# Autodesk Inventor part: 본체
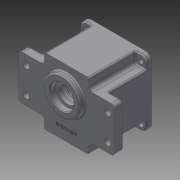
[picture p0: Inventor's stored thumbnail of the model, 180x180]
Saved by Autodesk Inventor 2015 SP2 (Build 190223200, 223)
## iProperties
Created: 2015-06
Part Number: 본체
Material: 일반
Document SubType Name: Modeling
Designer: AMC
Density: 1 g/cm^3
Appearance: 기본값
Author: AMC
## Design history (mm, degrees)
sketch "스케치4"
  geometry: L1 (-65, 30)-(65, 30); L2 (65, 30)-(65, -30); L3 (65, -30)-(-65, -30); L4 (-65, -30)-(-65, 30); 5 further points
  constraints: 8 end point, 4 midpoint, 2 horizontal alignment, 2 vertical alignment
  dimensions: "d22" = 130 distance of L2.end L3.end; "d23" = 60 distance of L1.end L2.end; "d24" = 60 distance of L3.end L1.start; "d25" = 130 distance of L1.start L1.end
extrude "돌출3" new body sketch "스케치4" distance "d26" = 12; taper "d27" = 0 deg
fillet "모깎기2" dims "d34" = 5
sketch "스케치10"
  geometry: L1 (30, -45)-(-30, -45); L2 (-30, -45)-(-30, 45); L3 (-30, 45)-(30, 45); L4 (30, 45)-(30, -45); 5 further points
  constraints: 8 end point, 4 midpoint, 2 horizontal alignment, 2 vertical alignment
  dimensions: "d57" = 60 distance of L2.end L3.end; "d58" = 90 distance of L1.end L2.end; "d59" = 60 distance of L1.start L1.end; "d60" = 90 distance of L3.end L1.start
extrude "돌출9" join sketch "스케치10" distance "d61" = 63; taper "d62" = 0 deg
sketch "스케치11"
  geometry: L1 (-30, -45)-(30, -45) reference; L2 (30, -45)-(30, 45) reference; L3 (30, 45)-(-30, 45) reference; L4 (-30, 45)-(-30, -45) reference; L5 (-45, 45)-(45, 45); L6 (45, 45)-(45, -45); L7 (45, -45)-(-45, -45); L8 (-45, -45)-(-45, 45); 5 further points
  constraints: 8 end point, 4 midpoint, 2 horizontal alignment, 2 vertical alignment
  dimensions: "d63" = 90 distance of L6.end L7.end; "d64" = 90 distance of L5.end L6.end; "d65" = 90 distance of L5.start L5.end; "d66" = 90 distance of L7.end L5.start
extrude "돌출10" join sketch "스케치11" distance "d67" = 7; taper "d68" = 0 deg
sketch "스케치12"
  geometry: L1 (-30, -45)-(-30, 45) reference; L2 (30, 45)-(30, -45) reference; L3 (30, -45)-(45, -45) reference; L4 (45, -45)-(45, 45) reference; L5 (45, 45)-(30, 45) reference; L6 (-30, 45)-(-45, 45) reference; L7 (-45, 45)-(-45, -45) reference; L8 (-45, -45)-(-30, -45) reference; C1 r 3.5 at (37, -37); C2 r 3.5 at (-37, -37); C3 r 3.5 at (-37, 37); C4 r 3.5 at (37, 37); 1 further point
  constraints: 4 centre point, 2 horizontal alignment, 2 vertical alignment
  dimensions: "d72" = 7 diameter of C1; "d73" = 7 diameter of C2; "d74" = 7 diameter of C3; "d75" = 7 diameter of C4; "d76" = 74 distance of C2.centre C1.centre; "d77" = 37 horizontal distance of point (0, 0) C1.centre; "d78" = 74 distance of C4.centre C1.centre; "d79" = 37 horizontal distance of point (0, 0) C4.centre
extrude "돌출11" cut sketch "스케치12" stored distance "d80" = 7; taper "d81" = 0 deg
sketch "스케치13"
  geometry: L1 (-60, -30)-(-30, -30) reference; L2 (65, -25)-(65, 25) reference; L3 (60, 30)-(30, 30) reference; L4 (30, 45)-(30, 30) reference; L5 (-30, 45)-(30, 45) reference; L6 (-30, -45)-(-30, -30) reference; L7 (-65, 25)-(-65, -25) reference; L8 (30, -45)-(-30, -45) reference; L9 (30, -30)-(60, -30) reference; L10 (-30, 30)-(-30, 45) reference; L11 (-30, 30)-(-60, 30) reference; L12 (30, -30)-(30, -45) reference; C1 r 4.5 at (55, -17.5); C2 r 4.5 at (-55, -17.5); C3 r 4.5 at (-55, 17.5); C4 r 4.5 at (55, 17.5); A1 r 5 centre (60, -25) between (60, -30) and (65, -25) reference; A2 r 5 centre (60, 25) between (65, 25) and (60, 30) reference; A3 r 5 centre (-60, 25) between (-60, 30) and (-65, 25) reference; A4 r 5 centre (-60, -25) between (-65, -25) and (-60, -30) reference; 1 further point
  constraints: 4 centre point, 2 horizontal alignment, 2 vertical alignment
  dimensions: "d82" = 9 diameter of C1; "d83" = 9 diameter of C2; "d84" = 9 diameter of C3; "d85" = 9 diameter of C4; "d86" = 110 distance of C1.centre C2.centre; "d87" = 55 horizontal distance of point (0, 0) C1.centre; "d88" = 35 distance of C1.centre C4.centre; "d89" = 17.5 vertical distance of C4.centre point (0, 0)
extrude "돌출12" cut sketch "스케치13" stored distance "d90" = 7; taper "d91" = 0 deg
sketch "스케치14"
  geometry: C1 r 25 at (0, -11); 1 further point
  constraints: 1 centre point, 1 vertical alignment
  dimensions: "d93" = 50 diameter of C1; "d94" = 11 distance of point (0, 0) C1.centre
extrude "돌출13" join sketch "스케치14" distance "d95" = 7; taper "d96" = 0 deg
fillet "모깎기9" dims "d97" = 2
sketch "스케치15"
  geometry: L1 (-38, 0)-(-45, 0) reference; L2 (-45, 0)-(-45, 70) reference; L3 (-45, 70)-(45, 70) reference; L4 (45, 70)-(45, 0) reference; L5 (45, 0)-(16, 0) reference; L6 (14, -2)-(14, -5) reference; L7 (12, -7)-(-34, -7) reference; L8 (-36, -5)-(-36, -2) reference; L9 (12, -7)-(-34, -7) reference; L10 (-11, -7)-(-11, 70); L11 (-11, -7)-(-27, -7); L12 (-27, -7)-(-27, 1); L13 (-27, 1)-(-23.5, 1); L14 (-23.5, 1)-(-23.5, 6); L15 (-23.5, 6)-(-28.5, 6); L16 (-28.5, 6)-(-28.5, 16); L17 (-28.5, 16)-(-11, 16); A1 r 2 centre (16, -2) between (14, -2) and (16, 0) reference; A2 r 2 centre (-38, -2) between (-38, 0) and (-36, -2) reference; A3 r 2 centre (12, -5) between (12, -7) and (14, -5) reference; A4 r 2 centre (-34, -5) between (-36, -5) and (-34, -7) reference; 1 further point
  constraints: 16 end point, 3 point on line, 1 midpoint
  dimensions: "d98" = 11 distance from line of L10 point (0, 0); "d99" = 32 diameter of L12 L10; "d100" = 25 diameter of L14 L10; "d101" = 35 diameter of L16 L10; "d102" = 8 distance of L11.end L12.end; "d103" = 10 distance of L15.end L16.end; "d104" = 5 distance of L13.end L14.end; "d105" = 23 distance between parallel lines of L17 L11; "d106" = 3.5 distance of L12.end L13.end
  node "절단 모서리 투영1"
sketch "스케치16"
  geometry: L1 (30, 45)-(30, -45) reference; L2 (45, -45)-(30, -45) reference; L3 (45, 45)-(45, -45) reference; L4 (30, 45)-(45, 45) reference; L5 (-30, 45)-(30, 45) reference; L6 (-30, -45)-(-30, 45) reference; L7 (-30, -45)-(-45, -45) reference; L8 (-45, -45)-(-45, 45) reference; L9 (-45, 45)-(-30, 45) reference; L10 (30, -45)-(-30, -45) reference; L11 (45, 45)-(45, -45) reference; L12 (-45, -45)-(-45, 45) reference; L13 (45, -30)-(-45, -30); L14 (-45, -30)-(-45, 30); L15 (-45, 30)-(45, 30); L16 (45, 30)-(45, -30); C1 r 3.5 at (37, -37) reference; C2 r 3.5 at (-37, -37) reference; C3 r 3.5 at (-37, 37) reference; C4 r 3.5 at (37, 37) reference; 4 further points
  constraints: 8 end point, 2 point on line, 1 horizontal alignment
  dimensions: "d121" = 60 distance between parallel lines of L15 L13; "d122" = 90 distance of L13.start L13.end; "d123" = 60 distance of L13.end L14.end; "d124" = 90 distance of L14.end L15.end
extrude "돌출14" join sketch "스케치16" stored distance "d125" = 7; taper "d126" = 0 deg
fillet "모깎기12" dims "d127" = 5
fillet "모깎기13" dims "d128" = 8
fillet "모깎기14" dims "d129" = 2
fillet "모깎기15" dims "d130" = 2
fillet "모깎기16" dims "d131" = 2
sketch "스케치18"
  geometry: C1 r 40 at (0, 0); 1 further point
  constraints: 1 centre point, 1 coincident
  dimensions: "d135" = 80 diameter of C1
extrude "돌출16" cut sketch "스케치18" distance "d136" = 9; taper "d137" = 0 deg
revolve "회전2" stored, may be unused: angle "d141" = 90 deg
sketch "스케치20"
  geometry: C1 r 39 at (0, 0); 1 further point
  constraints: 1 centre point, 1 coincident
  dimensions: "d142" = 78 diameter of C1
extrude "돌출18" cut sketch "스케치20" distance "d143" = 45; taper "d144" = 0 deg
sketch "스케치21"
  geometry: C1 r 11 at (0, 20); 1 further point
  constraints: 1 centre point, 1 vertical alignment
  dimensions: "d145" = 22 diameter of C1; "d146" = 20 distance of C1.centre point (0, 0)
extrude "돌출19" cut sketch "스케치21" distance "d147" = 7; taper "d148" = 0 deg
sketch "스케치22"
  geometry: L1 (-30, -65)-(-30, -55) reference; L2 (-35, -50)-(-60, -50) reference; L3 (-65, -45)-(-65, 5) reference; L4 (-60, 10)-(-35, 10) reference; L5 (-30, 15)-(-30, 25) reference; L6 (-30, 25)-(30, 25) reference; L7 (30, 25)-(30, 15) reference; L8 (35, 10)-(60, 10) reference; L9 (65, 5)-(65, -45) reference; L10 (60, -50)-(35, -50) reference; L11 (30, -55)-(30, -65) reference; L12 (30, -65)-(-30, -65) reference; C1 r 11 at (0, 0) reference; C2 r 17.5 at (0, -31) reference; C3 r 4.5 at (55, -2.5) reference; C4 r 4.5 at (-55, -37.5) reference; C5 r 4.5 at (55, -37.5) reference; C6 r 4.5 at (-55, -2.5) reference; C7 r 9.5 at (0, 0); A1 r 5 centre (-35, -55) between (-30, -55) and (-35, -50) reference; A2 r 5 centre (-60, -45) between (-65, -45) and (-60, -50) reference; A3 r 5 centre (-60, 5) between (-60, 10) and (-65, 5) reference; A4 r 5 centre (-35, 15) between (-35, 10) and (-30, 15) reference; A5 r 5 centre (35, 15) between (30, 15) and (35, 10) reference; A6 r 5 centre (60, 5) between (65, 5) and (60, 10) reference; A7 r 5 centre (60, -45) between (60, -50) and (65, -45) reference; A8 r 5 centre (35, -55) between (35, -50) and (30, -55) reference; 1 further point
  constraints: 1 centre point, 1 coincident
  dimensions: "d149" = 19 diameter of C7
extrude "돌출20" cut sketch "스케치22" distance "d150" = 1; taper "d151" = 0 deg
fillet "모깎기17" dims "d152" = 2
fillet "모깎기18" dims "d153" = 0.3
sketch "스케치23"
  geometry: L1 (0, 0)-(-24.749, -24.749); L2 (0, 0)-(35, 0); A1 r 39 centre (0, 0) between (-32.777, -21.134) and (-21.134, -32.777) reference; A2 r 35 centre (0, 0) between (-27.412, -21.762) and (-21.762, -27.412); A3 r 4 centre (-24.749, -24.749) between (-21.809, -27.462) and (-27.462, -21.809); A4 r 3.5 centre (-29.836, -19.238) between (-32.777, -21.134) and (-27.412, -21.762); A5 r 3.5 centre (-19.238, -29.836) between (-21.762, -27.412) and (-21.134, -32.777); A6 r 39 centre (0, 0) between (-32.777, -21.134) and (-21.134, -32.777); 1 further point
  constraints: 14 point on circle, 5 centre point, 4 end point, 4 tangent, 3 coincident, 1 equal length, 1 horizontal
  dimensions: "d154" = 70 diameter of A2; "d155" = 35 distance of L1.start L1.end; "d156" = 135 deg angle of L1 L2; "d157" = 8 diameter of A3; "d158" = 7 diameter of A4; "d159" = 7 diameter of A5
extrude "돌출21" join sketch "스케치23" stored distance "d161" = 1; taper "d162" = 0 deg
sketch "스케치24"
  geometry: C1 r 40 at (0, 0) reference; A1 r 39 centre (0, 0) between (-21.134, -32.777) and (-32.777, -21.134) reference; A2 r 3.5 centre (-19.238, -29.836) between (-21.809, -27.462) and (-21.134, -32.777) reference; A3 r 4 centre (-24.749, -24.749) between (-21.809, -27.462) and (-27.462, -21.809) reference; A4 r 3.5 centre (-29.836, -19.238) between (-32.777, -21.134) and (-27.462, -21.809) reference; 2 further points
  constraints: 1 coincident
hole "구멍1" sketch "스케치24" at (-24.749, -24.749) diameter "d163" = 3.242; stored, may be unused: countersink angle "d167" = 90 deg, drill point angle "d169" = 118 deg; dims "d164" = 12, "d165" = 4, "d166" = 2, "d168" = 15
sketch "스케치26"
  geometry: L1 (-30, -45)-(-30, -35) reference; L2 (-35, -30)-(-43, -30) reference; L3 (-45, -28)-(-45, 28) reference; L4 (-43, 30)-(-35, 30) reference; L5 (-30, 35)-(-30, 45) reference; L6 (-30, 45)-(30, 45) reference; L7 (30, 45)-(30, 35) reference; L8 (35, 30)-(43, 30) reference; L9 (45, 28)-(45, -28) reference; L10 (43, -30)-(35, -30) reference; L11 (30, -35)-(30, -45) reference; L12 (30, -45)-(-30, -45) reference; C1 r 11 at (0, 20) reference; C2 r 17.5 at (0, -11) reference; C3 r 39 at (0, 0); A1 r 3.5 centre (-19.238, 29.836) between (-21.134, 32.777) and (-21.809, 27.462) reference; A2 r 4 centre (-24.749, 24.749) between (-27.462, 21.809) and (-21.809, 27.462) reference; A3 r 3.5 centre (-29.836, 19.238) between (-27.462, 21.809) and (-32.777, 21.134) reference; A4 r 39 centre (0, 0) between (-32.777, 21.134) and (-32.777, -21.134) reference; A5 r 3.5 centre (-29.836, -19.238) between (-32.777, -21.134) and (-27.462, -21.809) reference; A6 r 4 centre (-24.749, -24.749) between (-21.809, -27.462) and (-27.462, -21.809) reference; A7 r 3.5 centre (-19.238, -29.836) between (-21.809, -27.462) and (-21.134, -32.777) reference; A8 r 39 centre (0, 0) between (-21.134, -32.777) and (21.134, -32.777) reference; A9 r 3.5 centre (19.238, -29.836) between (21.134, -32.777) and (21.809, -27.462) reference; A10 r 4 centre (24.749, -24.749) between (27.462, -21.809) and (21.809, -27.462) reference; A11 r 3.5 centre (29.836, -19.238) between (27.462, -21.809) and (32.777, -21.134) reference; A12 r 39 centre (0, 0) between (32.777, -21.134) and (32.777, 21.134) reference; A13 r 3.5 centre (29.836, 19.238) between (32.777, 21.134) and (27.462, 21.809) reference; A14 r 4 centre (24.749, 24.749) between (21.809, 27.462) and (27.462, 21.809) reference; A15 r 3.5 centre (19.238, 29.836) between (21.809, 27.462) and (21.134, 32.777) reference; A16 r 39 centre (0, 0) between (21.134, 32.777) and (-21.134, 32.777) reference; A17 r 5 centre (-35, -35) between (-30, -35) and (-35, -30) reference; A18 r 2 centre (-43, -28) between (-45, -28) and (-43, -30) reference; A19 r 2 centre (-43, 28) between (-43, 30) and (-45, 28) reference; A20 r 5 centre (-35, 35) between (-35, 30) and (-30, 35) reference; A21 r 5 centre (35, 35) between (30, 35) and (35, 30) reference; A22 r 2 centre (43, 28) between (45, 28) and (43, 30) reference; A23 r 2 centre (43, -28) between (43, -30) and (45, -28) reference; A24 r 5 centre (35, -35) between (35, -30) and (30, -35) reference; A25 r 20.5 centre (0, -11) between (-7.402, 8.117) and (7.402, 8.117); A26 r 14 centre (0, 20) between (7.402, 8.117) and (-7.402, 8.117); 1 further point
  constraints: 4 point on circle, 3 centre point, 3 coincident
  dimensions: "d175" = 41 diameter of A25; "d176" = 78 diameter of C3; "d177" = 28 diameter of A26
extrude "돌출23" cut sketch "스케치26" distance "d178" = 7; taper "d179" = 0 deg
fillet "모깎기19" dims "d180" = 3
sketch "스케치27"
  geometry: L1 (30, -35)-(30, -43) reference; L2 (30, -43)-(30, -45) reference; L3 (30, -45)-(-30, -45) reference; L4 (-30, -45)-(-30, -43) reference; L5 (-30, -43)-(-30, -35) reference; L6 (-35, -30)-(-43, -30) reference; L7 (-45, -28)-(-45, 28) reference; L8 (-43, 30)-(-35, 30) reference; L9 (-30, 35)-(-30, 43) reference; L10 (-30, 43)-(-30, 45) reference; L11 (-30, 45)-(30, 45) reference; L12 (30, 45)-(30, 43) reference; L13 (30, 43)-(30, 35) reference; L14 (35, 30)-(43, 30) reference; L15 (45, 28)-(45, -28) reference; L16 (43, -30)-(35, -30) reference; C1 r 1.621 at (24.749, -24.749) reference; C2 r 1.621 at (24.749, 24.749) reference; C3 r 1.621 at (-24.749, 24.749) reference; C4 r 1.621 at (-24.749, -24.749) reference; C5 r 40 at (0, 0) reference; A1 r 39 centre (0, 0) between (32.777, -21.134) and (32.777, 21.134) reference; A2 r 3.5 centre (29.836, 19.238) between (32.777, 21.134) and (27.462, 21.809) reference; A3 r 4 centre (24.749, 24.749) between (21.809, 27.462) and (27.462, 21.809) reference; A4 r 3.5 centre (19.238, 29.836) between (21.809, 27.462) and (21.134, 32.777) reference; A5 r 39 centre (0, 0) between (21.134, 32.777) and (-21.134, 32.777) reference; A6 r 3.5 centre (-19.238, 29.836) between (-21.134, 32.777) and (-21.809, 27.462) reference; A7 r 4 centre (-24.749, 24.749) between (-27.462, 21.809) and (-21.809, 27.462) reference; A8 r 3.5 centre (-29.836, 19.238) between (-27.462, 21.809) and (-32.777, 21.134) reference; A9 r 39 centre (0, 0) between (-32.777, 21.134) and (-32.777, -21.134) reference; A10 r 3.5 centre (-29.836, -19.238) between (-32.777, -21.134) and (-27.462, -21.809) reference; A11 r 4 centre (-24.749, -24.749) between (-21.809, -27.462) and (-27.462, -21.809) reference; A12 r 3.5 centre (-19.238, -29.836) between (-21.809, -27.462) and (-21.134, -32.777) reference; A13 r 39 centre (0, 0) between (-21.134, -32.777) and (21.134, -32.777) reference; A14 r 3.5 centre (19.238, -29.836) between (21.134, -32.777) and (21.809, -27.462) reference; A15 r 4 centre (24.749, -24.749) between (27.462, -21.809) and (21.809, -27.462) reference; A16 r 3.5 centre (29.836, -19.238) between (27.462, -21.809) and (32.777, -21.134) reference; A17 r 5 centre (-35, -35) between (-30, -35) and (-35, -30) reference; A18 r 2 centre (-43, -28) between (-45, -28) and (-43, -30) reference; A19 r 2 centre (-43, 28) between (-43, 30) and (-45, 28) reference; A20 r 5 centre (-35, 35) between (-35, 30) and (-30, 35) reference; A21 r 5 centre (35, 35) between (30, 35) and (35, 30) reference; A22 r 2 centre (43, 28) between (45, 28) and (43, 30) reference; A23 r 2 centre (43, -28) between (43, -30) and (45, -28) reference; A24 r 5 centre (35, -35) between (35, -30) and (30, -35) reference; 1 further point
extrude "돌출24" join sketch "스케치27" stored distance "d181" = 7; taper "d182" = 0 deg
chamfer "모따기2" distance "d183" = 1; stored, may be unused: second distance "d184" = 2, angle "d185" = 45 deg
fillet "모깎기20" dims "d186" = 2
fillet "모깎기21" dims "d187" = 2
fillet "모깎기22" dims "d188" = 0.3
sketch "스케치28"
  geometry: L1 (-30, 45)-(30, 45) reference; 2 further points
  constraints: 1 vertical alignment, 1 other
  dimensions: "d189" = 15 distance from line of L1 point (0, 30)
feature "엠보싱1" sketch "스케치28" dims "d62" = 0, "d190" = 0.5, "d191" = 0
fillet "모깎기23" dims "d192" = 2
fillet "모깎기24" dims "d193" = 3
node "솔리드2"
pattern_circular "원형 패턴1" dims angle "d171" = 360 deg
node "투영된 루프10"
node "투영된 루프11"
node "투영된 루프12"
node "투영된 루프13"
node "투영된 루프14"
node "절단 모서리 투영2"
node "절단 모서리 투영3"
node "절단 모서리 투영4"
node "절단 모서리 투영5"
